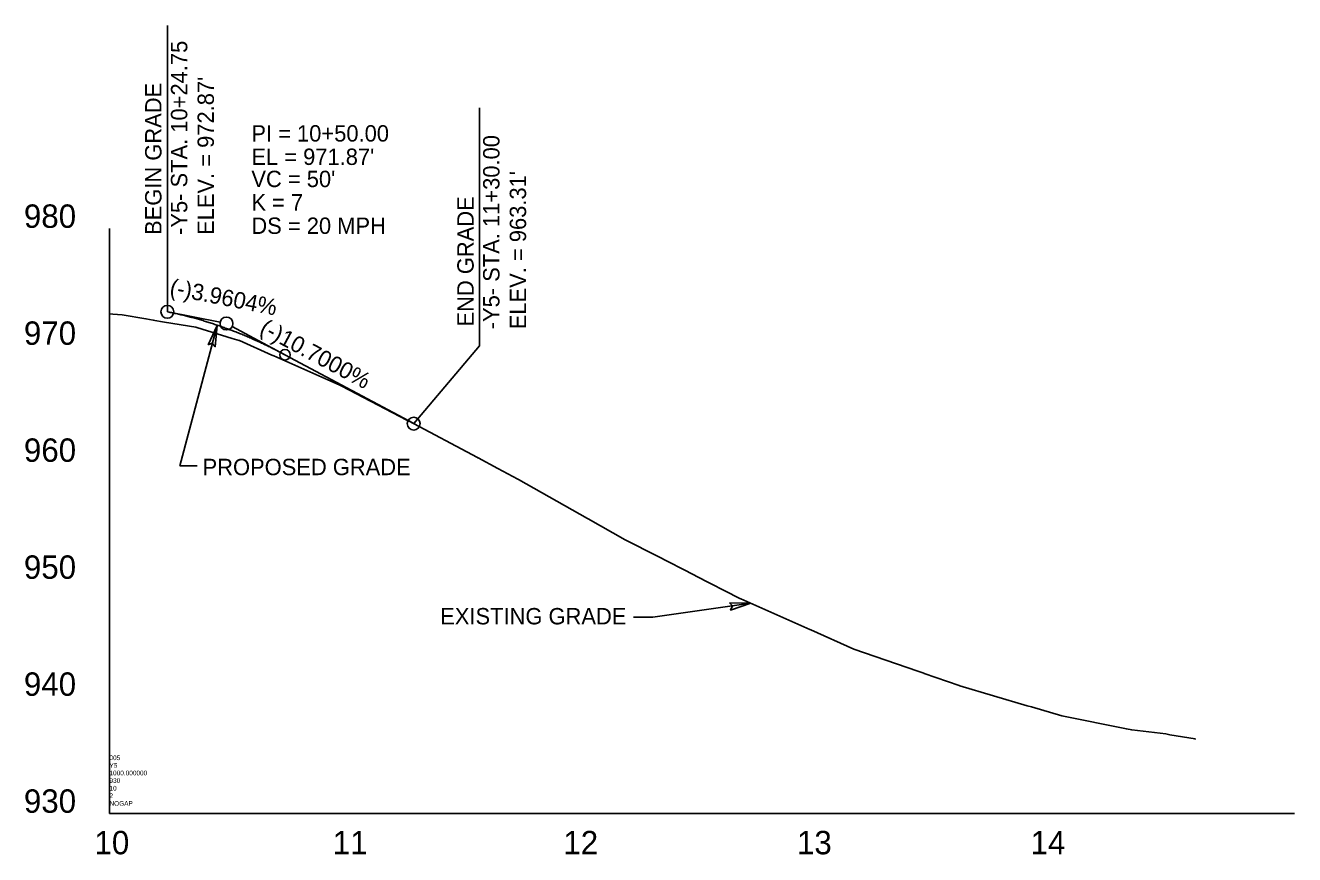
# Model space of a CAD drawing. Extents: x 1615624 to 1632571, y 894455 to 913418.
# Drawn here: x 1629561 to 1630103, y 897606 to 897960 of the extents above; entities that cross this region are included whole.
import ezdxf

# ---------------------------------------------------------------- set-up
doc = ezdxf.new("R2010")
doc.units = 0
for name, color, linetype in [('Exist Profile Cell', 7, 'Continuous'), ('Exist Vertical Profile Ground Line', 7, 'Continuous'), ('Exist Vertical Profile Horizontal Axis Label Major', 7, 'Continuous'), ('Exist Vertical Profile Vertical Axis Label', 7, 'Continuous'), ('Prop Terminator CELL', 7, 'Continuous'), ('Prop Vertical Profile Curve Label', 7, 'Continuous'), ('Prop Vertical Profile Grade', 7, 'Continuous'), ('Prop Vertical Profile Grade Label', 7, 'Continuous'), ('Prop VPI Label', 7, 'Continuous')]:
    doc.layers.add(name, color=color, linetype=linetype)

msp = doc.modelspace()

# ---------------------------------------------------------------- linework, layer by layer
at = {"layer": 'Exist Profile Cell'}
for q in [(1629596.56, 897873.42), (1630103.05, 897623.42), (1629596.56, 897623.42)]:
    msp.add_line((1629596.56, 897623.42), q, dxfattribs=at)
at = {"layer": 'Exist Vertical Profile Ground Line'}
msp.add_lwpolyline([(1629596.56, 897836.86), (1629597.98, 897836.76), (1629601.93, 897836.48), (1629612.14, 897834.79), (1629615.24, 897834.23), (1629615.9, 897834.07), (1629619.15, 897833.5), (1629620.02, 897833.39), (1629633.46, 897831.16), (1629633.9, 897831.01), (1629648.98, 897826.44), (1629651.97, 897825.53), (1629652.03, 897825.51), (1629652.09, 897825.48), (1629665.97, 897819.32), (1629665.99, 897819.31), (1629666.78, 897818.96), (1629694.97, 897806.39), (1629695.88, 897805.98), (1629723.65, 897791.54), (1629724.18, 897791.27), (1629724.39, 897791.14), (1629724.41, 897791.13), (1629753.78, 897775.51), (1629753.91, 897775.43), (1629753.93, 897775.42), (1629754.06, 897775.34), (1629762.5, 897770.85), (1629771.02, 897766.32), (1629771.16, 897766.26), (1629771.33, 897766.16), (1629800.88, 897749.46), (1629801.07, 897749.35), (1629816.98, 897740.35), (1629817.19, 897740.25), (1629830.49, 897733.44), (1629846.56, 897725.23), (1629846.82, 897725.09), (1629846.99, 897725), (1629865.96, 897715.3), (1629866.33, 897715.14), (1629895.84, 897702), (1629896.31, 897701.79), (1629914.69, 897693.6), (1629942.04, 897684.15), (1629944.58, 897683.27), (1629944.66, 897683.24), (1629959.72, 897678.04), (1629960.03, 897677.95), (1629988.74, 897669.4), (1629990.53, 897668.93), (1630003.57, 897665.07), (1630031.14, 897659.5), (1630033.44, 897659.05), (1630048.02, 897657.37), (1630049.71, 897657.04), (1630060.5, 897655.28), (1630060.56, 897655)], dxfattribs=at)
at = {"layer": 'Prop Terminator CELL'}
for points in [[(1629638.72, 897823.7), (1629642.53, 897832), (1629641.75, 897822.85), (1629640.5, 897824.37)], [(1629861.58, 897713.46), (1629870.7, 897713.19), (1629861.97, 897710.33), (1629862.88, 897712.08)]]:
    msp.add_lwpolyline(points, close=True, dxfattribs=at)
at = {"layer": 'Prop Vertical Profile Curve Label'}
msp.add_circle((1629671.56, 897819.41), 2.25, dxfattribs=at)
at = {"layer": 'Prop Vertical Profile Grade'}
for p, q in [((1629621.31, 897837.78), (1629621.56, 897837.73)), ((1629671.56, 897819.41), (1629726.56, 897789.98))]:
    msp.add_line(p, q, dxfattribs=at)
msp.add_spline([(1629621.56, 897837.73), (1629622.56, 897837.53), (1629623.56, 897837.32), (1629624.56, 897837.11), (1629625.56, 897836.88), (1629626.56, 897836.66), (1629627.56, 897836.42), (1629628.56, 897836.18), (1629629.56, 897835.93), (1629630.56, 897835.68), (1629631.56, 897835.41), (1629632.56, 897835.15), (1629633.56, 897834.87), (1629634.56, 897834.59), (1629635.56, 897834.3), (1629636.56, 897834), (1629637.56, 897833.7), (1629638.56, 897833.39), (1629639.56, 897833.08), (1629640.56, 897832.75), (1629641.56, 897832.42), (1629642.56, 897832.09), (1629643.56, 897831.75), (1629644.56, 897831.4), (1629645.56, 897831.04), (1629646.56, 897830.68), (1629647.56, 897830.31), (1629648.56, 897829.93), (1629649.56, 897829.55), (1629650.56, 897829.16), (1629651.56, 897828.76), (1629652.56, 897828.36), (1629653.56, 897827.95), (1629654.56, 897827.53), (1629655.56, 897827.11), (1629656.56, 897826.68), (1629657.56, 897826.24), (1629658.56, 897825.79), (1629659.56, 897825.34), (1629660.56, 897824.89), (1629661.56, 897824.42), (1629662.56, 897823.95), (1629663.56, 897823.47), (1629664.56, 897822.99), (1629665.56, 897822.5), (1629666.56, 897822), (1629667.56, 897821.5), (1629668.56, 897820.98), (1629669.56, 897820.47), (1629670.56, 897819.94), (1629671.56, 897819.41)], degree=3, dxfattribs=at)
at = {"layer": 'Prop VPI Label'}
for p, q in [((1629621.31, 897837.78), (1629621.31, 897960.2)), ((1629754.72, 897823.25), (1629754.72, 897924.9)), ((1629621.56, 897837.73), (1629643.86, 897833.32)), ((1629642.53, 897832), (1629626.59, 897772)), ((1629671.56, 897819.41), (1629648.99, 897831.49)), ((1629726.56, 897789.98), (1629754.72, 897823.25)), ((1629626.59, 897772), (1629634.01, 897772)), ((1629870.7, 897713.19), (1629828.79, 897707.22)), ((1629828.79, 897707.22), (1629820.53, 897707.22))]:
    msp.add_line(p, q, dxfattribs=at)
for centre in [(1629621.31, 897837.78), (1629646.56, 897832.78), (1629726.56, 897789.98)]:
    msp.add_circle(centre, 2.75, dxfattribs=at)

# ---------------------------------------------------------------- texts
at = {"layer": 'Exist Profile Cell'}
for s, p in [('005', (1629596.56, 897646.17)), ('Y5', (1629596.56, 897642.92)), ('930', (1629596.56, 897636.42)), ('1000.000000', (1629596.56, 897639.67)), ('2', (1629596.56, 897629.92)), ('10', (1629596.56, 897633.17)), ('NOGAP', (1629596.56, 897626.67))]:
    msp.add_text(s, height=2, dxfattribs=at).set_placement(p)
at = {"layer": 'Exist Vertical Profile Horizontal Axis Label Major'}
for s, p in [('10', (1629590.15, 897605.92)), ('11', (1629691.98, 897605.92)), ('12', (1629790.53, 897605.92)), ('13', (1629890.37, 897605.92)), ('14', (1629990.21, 897605.92))]:
    msp.add_text(s, height=10, dxfattribs=at).set_placement(p)
at = {"layer": 'Exist Vertical Profile Vertical Axis Label'}
for s, p in [('980', (1629559.99, 897873.67)), ('970', (1629559.99, 897823.67)), ('960', (1629559.99, 897773.67)), ('950', (1629559.99, 897723.67)), ('940', (1629559.99, 897673.67)), ('930', (1629559.99, 897623.67))]:
    msp.add_text(s, height=10, dxfattribs=at).set_placement(p)
at = {"layer": 'Prop Vertical Profile Grade Label'}
for s, rotation, p in [('(-)3.9604%', 348.8101, (1629621.95, 897845.12)), ('(-)10.7000%', 331.8532, (1629660.26, 897828.86))]:
    msp.add_text(s, height=7, rotation=rotation, dxfattribs=at).set_placement(p)
at = {"layer": 'Prop VPI Label'}
for s, p in [('-Y5- STA. 10+24.75', (1629629.82, 897870.64)), ('BEGIN GRADE', (1629618.78, 897870.64)), ("ELEV. = 972.87'", (1629641.2, 897870.64)), ('-Y5- STA. 11+30.00', (1629763.23, 897830.33)), ("ELEV. = 963.31'", (1629774.61, 897830.33)), ('END GRADE', (1629752.2, 897831.51))]:
    msp.add_text(s, height=7, rotation=90, dxfattribs=at).set_placement(p)
for s, p in [('PI = 10+50.00', (1629657.2, 897910.55)), ("EL = 971.87'", (1629657.2, 897900.55)), ("VC = 50'", (1629657.2, 897891.08)), ('K = 7', (1629657.2, 897881.08)), ('DS = 20 MPH', (1629657.2, 897871.08)), ('PROPOSED GRADE', (1629636.35, 897767.96)), ('EXISTING GRADE', (1629737.9, 897704.18))]:
    msp.add_text(s, height=7, dxfattribs=at).set_placement(p)

doc.saveas('drawing.dxf')
